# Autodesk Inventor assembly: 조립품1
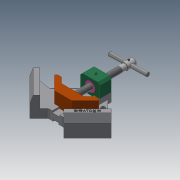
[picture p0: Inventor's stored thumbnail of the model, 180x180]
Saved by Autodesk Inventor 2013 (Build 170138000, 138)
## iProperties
Created: 2020-05
Part Number: 조립품1
Document SubType Name: Assembly
Designer: user
Author: user
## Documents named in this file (11)
- C:\Users\user\Desktop\700506V1004\조립품1.iam
- C:\Users\user\Desktop\700506V1004\700506V1004 부품.ipt
- C:\Users\user\Desktop\700506V1004\리드스크류.ipt
- C:\Users\user\Desktop\700506V1004\멈춤나사 M4x5.ipt
- C:\Users\user\Desktop\700506V1004\멈춤나사 M4x10.ipt
- C:\Users\user\Desktop\700506V1004\볼트 M4x16.ipt
- C:\Users\user\Desktop\700506V1004\부시.ipt
- C:\Users\user\Desktop\700506V1004\서포트.ipt
- C:\Users\user\Desktop\700506V1004\조.ipt
- C:\Users\user\Desktop\700506V1004\평행 핀 2.5x24.ipt
- C:\Users\user\Desktop\700506V1004\핸들.ipt
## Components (2 placed, 2 different names)
1. 700506V1004 부품:1
2. 핸들:1
